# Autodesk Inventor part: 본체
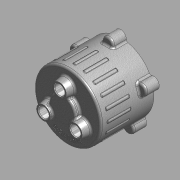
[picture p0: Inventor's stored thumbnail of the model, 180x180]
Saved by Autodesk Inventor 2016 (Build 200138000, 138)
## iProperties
Created: 2015-11
Part Number: 본체
Document SubType Name: 모델링
Designer: mdu
Material: 일반
Density: 1 g/cm^3
Appearance: 기본값
변환 표준: STEP AP214IS
파일 이름: C:\Users\SeoGD\Desktop\?쒗뿕\紐몄껜.stp
전처리기: Build: 253, Release: 2010 SP1 - Date: Wed 07/29/2009
전송 단위: 밀리미터
불확실성: 0.01
Author: mdu
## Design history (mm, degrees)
sketch "스케치2"
  geometry: C1 r 50 at (0, 0); 1 further point
  constraints: 1 centre point, 1 coincident
  dimensions: "d9" = 100 diameter of C1
extrude "돌출2" new body sketch "스케치2" distance "d10" = 80; taper "d11" = 0 deg
feature "쉘1" dims "d12" = 5
sketch "스케치3" dims "d13" = 55
  geometry: C1 r 7.5 at (0, 27.5); C2 r 12.5 at (0, 27.5); 2 further points
  constraints: 2 centre point, 2 coincident, 2 vertical alignment, 2 other
  dimensions: "d14" = 15 diameter of C1; "d15" = 25 diameter of C2
extrude "돌출3" join sketch "스케치3" distance "d16" = 12; taper "d17" = -10 deg
hole "구멍2" diameter "d20" = 15; stored, may be unused: countersink angle "d24" = 90 deg, drill point angle "d26" = 118 deg; dims "d18" = 10, "d19" = 10, "d21" = 6, "d22" = 4, "d23" = 2, "d25" = 15
chamfer "모따기1" distance "d27" = 1; stored, may be unused: second distance "d28" = 2, angle "d29" = 45 deg
sketch "스케치4"
  geometry: L1 (0, 0)-(0, 88); L2 (0, 70)-(13.16, 70); L3 (-45, 75)-(45, 75) reference; L4 (-50, 80)-(50, 80) reference; L5 (13.16, 70)-(14.5, 75); L6 (20, 80)-(20, 88); L7 (20, 88)-(0, 88); L8 (20, 80)-(14.5, 75)
  constraints: 12 end point, 3 point on line, 2 perpendicular, 1 vertical
  dimensions: "d34" = 40 diameter of L6 L1; "d35" = 105 deg angle of L5 L3; "d36" = 5 distance between parallel lines of L2 L3; "d37" = 8 distance between parallel lines of L7 L4; "d51" = 29 diameter of L5.end L1
revolve "회전1" sketch "스케치4" stored, may be unused: angle "d38" = 90 deg
hole "구멍3" diameter "d41" = 15; stored, may be unused: countersink angle "d45" = 90 deg, drill point angle "d47" = 0 deg; dims "d39" = 10, "d40" = 10, "d42" = 6, "d43" = 22, "d44" = 13, "d46" = 15
chamfer "모따기2" distance "d48" = 1; stored, may be unused: second distance "d49" = 2, angle "d50" = 45 deg
fillet "모깎기1" dims "d52" = 3
fillet "모깎기2" dims "d53" = 3, "d72" = 0.2
sketch "스케치5"
  geometry: A1 r 50 centre (0, 0) between (50, 0) and (-8.074, 49.344) reference; A2 r 8.5 centre (0, 52) between (8.074, 49.344) and (-8.074, 49.344); 1 further point
  constraints: 5 point on circle, 1 centre point, 1 horizontal alignment
  dimensions: "d54" = 90 deg dimension on point (0, 0) A2.centre A1.start; "d55" = 52 distance of A2.centre point (0, 0); "d56" = 17 diameter of A2
extrude "돌출4" join sketch "스케치5" distance "d57" = 20; taper "d58" = 0 deg
fillet "모깎기3" dims "d59" = 3
hole "구멍4" diameter "d62" = 4.134; stored, may be unused: countersink angle "d66" = 90 deg, drill point angle "d68" = 118 deg; dims "d60" = 10, "d61" = 10, "d63" = 12, "d64" = 22, "d65" = 13, "d67" = 15
sketch "스케치6"
  geometry: C1 r 47 at (0, 0) reference; C2 r 42.5 at (0, 0); 1 further point
  constraints: 1 centre point, 1 coincident, 1 other
  dimensions: "d73" = 85 diameter of C2
feature "엠보싱1" sketch "스케치6" dims "d74" = 0.5, "d75" = 0
node "작업 평면1"
sketch "스케치7"
  geometry: A1 r 50 centre (0, 0) between (5.144, 49.735) and (-5.144, 49.735) reference; A2 r 3 centre (0, 47.916) between (2.204, 49.951) and (-2.204, 49.951); 1 further point
  constraints: 4 point on circle, 1 centre point, 1 vertical alignment
  dimensions: "d77" = 3 radius of A2
extrude "돌출5" join sketch "스케치7" distance "d79" = 35; taper "d80" = 0 deg
fillet "모깎기4" dims "d81" = 1
fillet "모깎기5" dims "d82" = 1
node "솔리드1"
node "솔리드 본체"
node "곡면 본체"
pattern_circular "원형 패턴1" dims "d31" = 360 deg
pattern_circular "원형 패턴2" dims "d70" = 360 deg
pattern_circular "원형 패턴3" dims "d84" = 360 deg
node "솔리드2"
